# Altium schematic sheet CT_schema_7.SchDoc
size 301 x 177 mm
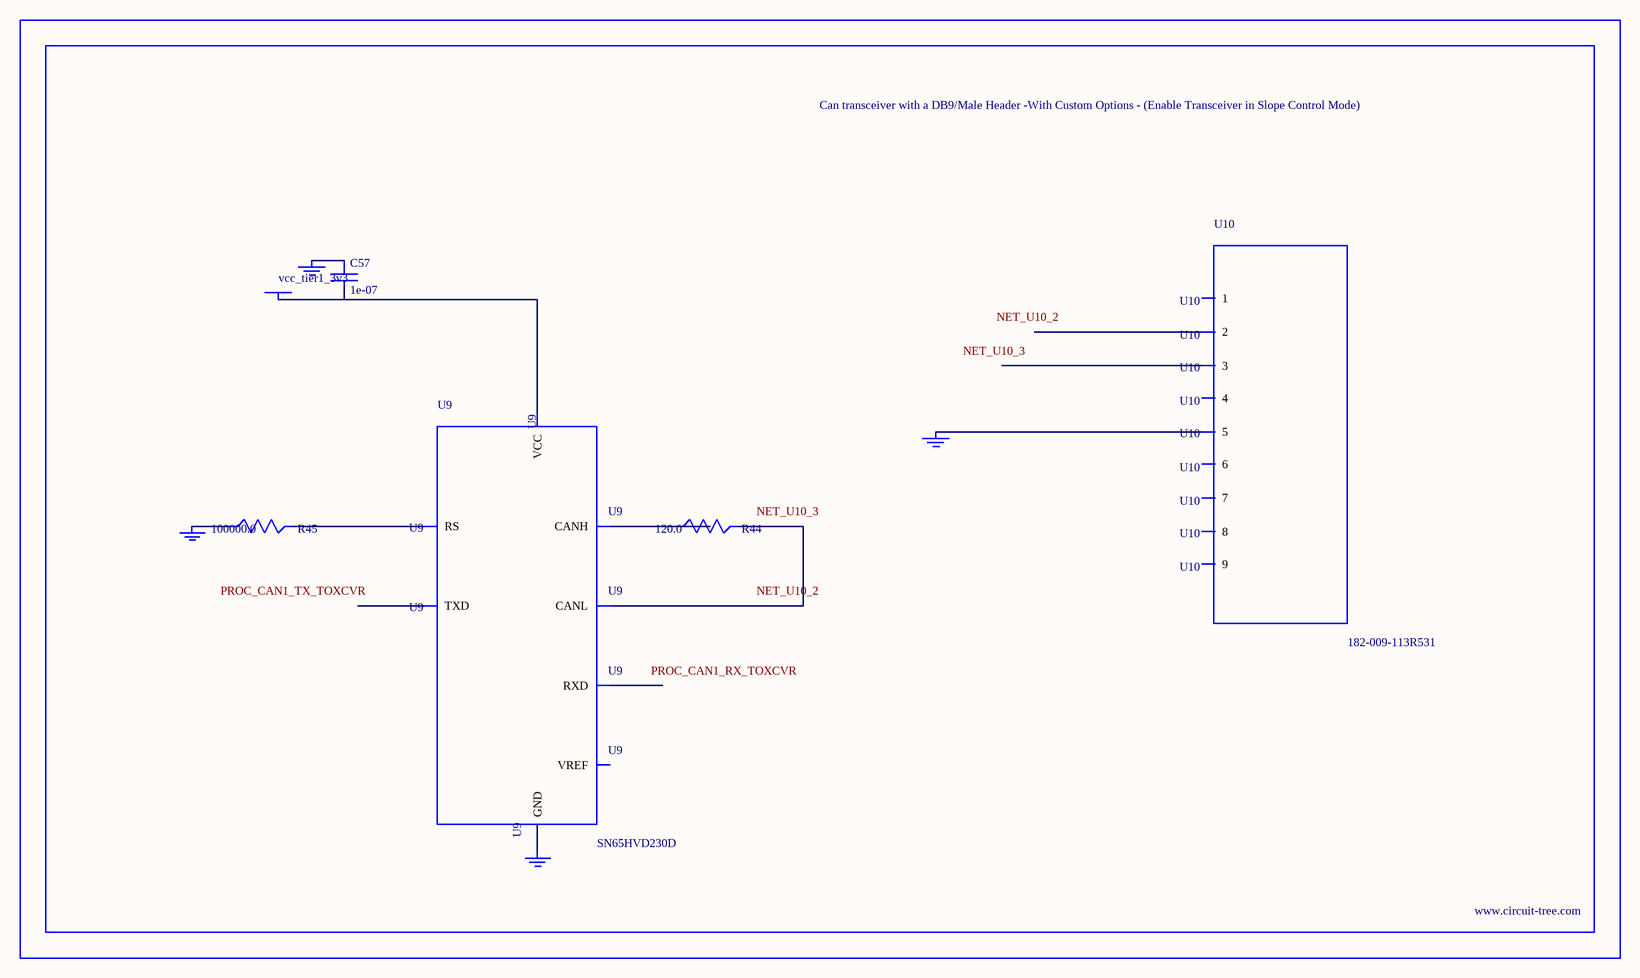
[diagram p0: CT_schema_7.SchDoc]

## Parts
BORDER6  (no value)
C57  1e-07  [C0402]
GND_INSTANCE_6_0  (no value)
GND_INSTANCE_6_1  (no value)
GND_INSTANCE_6_2  (no value)
GND_INSTANCE_6_3  (no value)
POWER_INSTANCE_6_0  vcc_tier1_3v3
R44  120.0  [R0603]
R45  100000.0  [R0603]
U9  SN65HVD230D  [SOIC-8]
U10  182-009-113R531  [182-009-MALE]

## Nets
NetC57_1: C57.1 GND_INSTANCE_6_0.0(GND)
NetC57_2: C57.2 POWER_INSTANCE_6_0.0(PWR) U9.3(VCC)
NetGND_INSTANCE_6_1_0: GND_INSTANCE_6_1.0(GND) R45.1
NetGND_INSTANCE_6_2_0: GND_INSTANCE_6_2.0(GND) U9.2(GND)
NetGND_INSTANCE_6_3_0: GND_INSTANCE_6_3.0(GND) U10.5
NetR44_1: R44.1 U9.7(CANH)
NetR44_2: R44.2 U9.6(CANL)
NetR45_2: R45.2 U9.8(RS)

Not connected (* = marked no-connect by the designer): U9 1(TXD) 4(RXD) 5(VREF); U10 1 2 3 4 6 7 8 9

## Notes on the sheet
- Labels drawn without touching a wire or pin: NET_U10_2, NET_U10_3, PROC_CAN1_RX_TOXCVR, PROC_CAN1_TX_TOXCVR

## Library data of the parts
BORDER6 = BORDER_PAGE6
C57 = C0402C104K3RACTU
GND_INSTANCE_6_0-GND_INSTANCE_6_3 = GND
POWER_INSTANCE_6_0 = PWR
R44 = RC0603JR-07120RL
R45 = RC0603JR-07100KL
